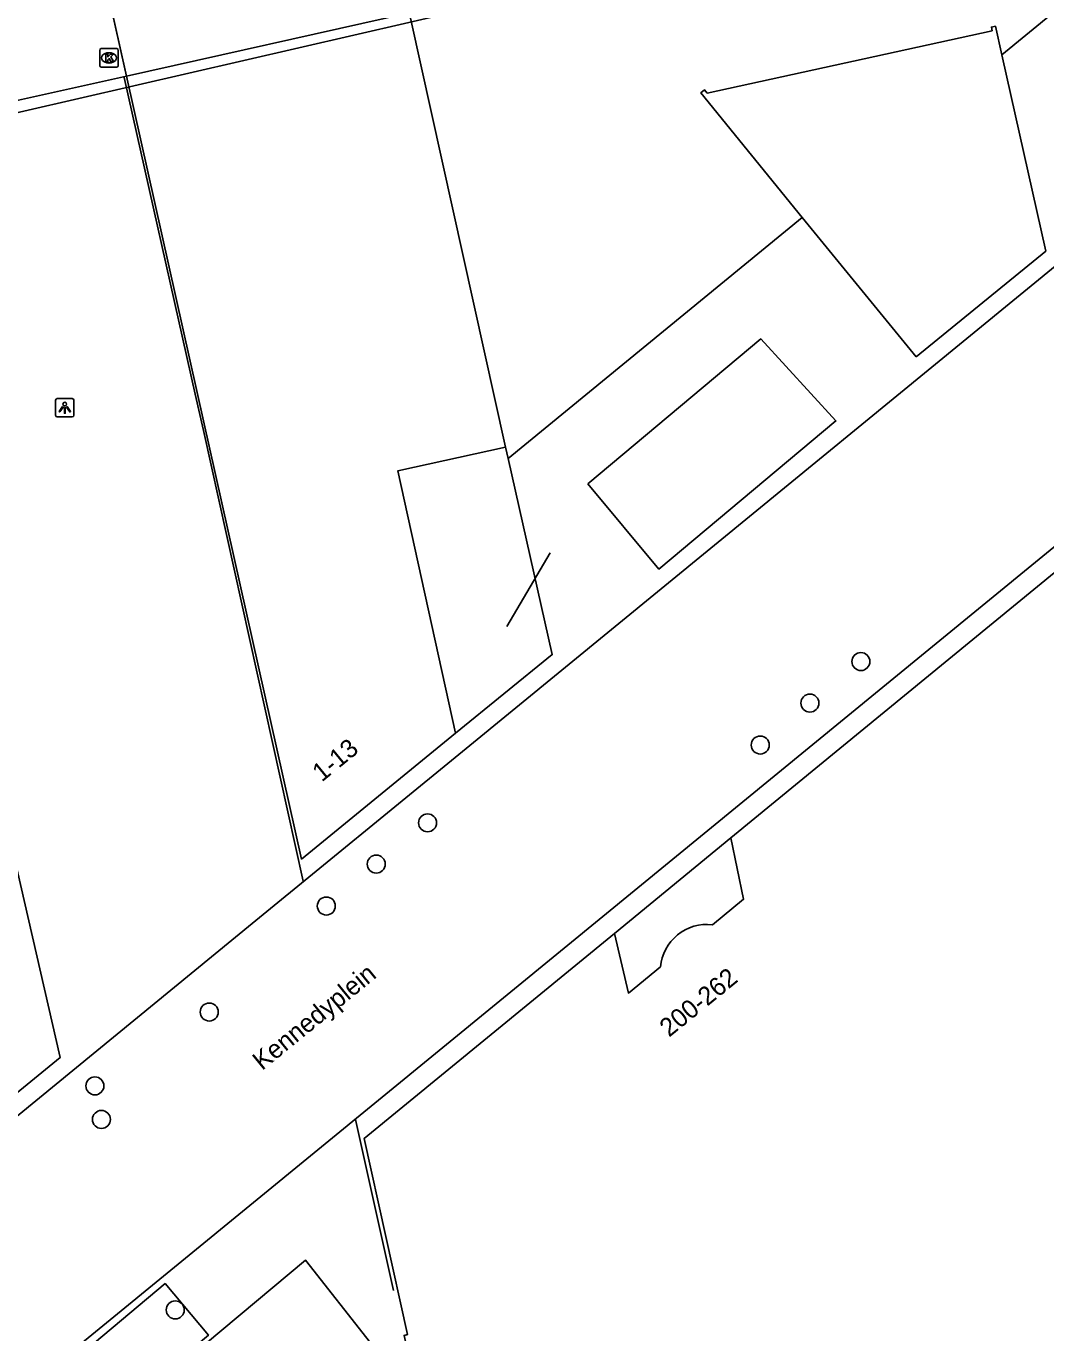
# Model space of a CAD drawing. Extents: x 160806 to 161707, y 383697 to 384148.
# Drawn here: x 161433.9 to 161489.3, y 383859.4 to 383930.4 of the extents above; entities that cross this region are included whole.
import ezdxf

# ---------------------------------------------------------------- set-up
doc = ezdxf.new("R2010")
doc.units = 0
for name, color, linetype in [('IMGEO_Boom', 7, 'Continuous'), ('IMGEO_Kolk', 7, 'Continuous'), ('IMGEO_Lage_trafo', 7, 'Continuous'), ('IMGEO_Lichtpunt', 7, 'Continuous'), ('IMGEO_Lijnafwatering', 7, 'Continuous'), ('IMGEO_Muur', 7, 'Continuous'), ('IMGEO_Openbare_ruimte_label', 7, 'Continuous'), ('IMGEO_Pand', 7, 'Continuous'), ('IMGEO_Pand_nummerreeks', 7, 'Continuous'), ('IMGEO_Pand_overbouw', 7, 'Continuous'), ('IMGEO_Pand_vergunning_verleend', 7, 'Continuous'), ('IMGEO_Rijbaan_lokaal_open', 7, 'Continuous'), ('IMGEO_Voetpad_open', 7, 'Continuous')]:
    doc.layers.add(name, color=color, linetype=linetype)

msp = doc.modelspace()

# ---------------------------------------------------------------- linework, layer by layer
at = {"layer": 'IMGEO_Boom'}
for centre in [(161479.28, 383895.862), (161476.511, 383893.603), (161473.815, 383891.327), (161455.746, 383887.101), (161452.959, 383884.86), (161450.245, 383882.583), (161443.887, 383876.827), (161437.673, 383872.817), (161438.028, 383870.992), (161442.039, 383860.652)]:
    msp.add_circle(centre, 0.489, dxfattribs=at)
at = {"layer": 'IMGEO_Kolk'}
for p, q in [((161437.942, 383928.219), (161437.942, 383929.071)), ((161438.017, 383929.145), (161438.869, 383929.145)), ((161438.43, 383928.925), (161438.455, 383928.925)), ((161438.943, 383929.071), (161438.943, 383928.219)), ((161438.869, 383928.145), (161438.017, 383928.145)), ((161438.453, 383928.365), (161438.428, 383928.365))]:
    msp.add_line(p, q, dxfattribs=at)
for points in [[(161437.942, 383928.219), (161437.942, 383929.071)], [(161438.017, 383929.145), (161438.869, 383929.145)], [(161438.263, 383928.845), (161438.386, 383928.845), (161438.386, 383928.694), (161438.516, 383928.845), (161438.68, 383928.845), (161438.534, 383928.694), (161438.687, 383928.445), (161438.535, 383928.445), (161438.45, 383928.609), (161438.386, 383928.542), (161438.386, 383928.445), (161438.263, 383928.445), (161438.263, 383928.845)], [(161438.943, 383929.071), (161438.943, 383928.219)], [(161438.869, 383928.145), (161438.017, 383928.145)]]:
    msp.add_lwpolyline(points, dxfattribs=at)
for centre, start, end in [((161438.019, 383929.069), 91.55205, 178.44795), ((161438.019, 383929.069), 91.55205, 178.44795), ((161438.867, 383929.069), 1.55205, 88.44795), ((161438.867, 383929.069), 1.55205, 88.44795), ((161438.019, 383928.221), 181.55205, 268.44795), ((161438.019, 383928.221), 181.55205, 268.44795), ((161438.867, 383928.221), 271.55205, 358.44795), ((161438.867, 383928.221), 271.55205, 358.44795)]:
    msp.add_arc(centre, 0.0765, start, end, dxfattribs=at)
for centre, major_axis, ratio, start_param, end_param in [((161438.429, 383928.645), (-0.387, 0.002), 0.722429, 4.712389, 7.853982), ((161438.454, 383928.645), (-0.39, 0.002), 0.717154, 1.570796, 4.712389)]:
    msp.add_ellipse(centre, major_axis=major_axis, ratio=ratio, start_param=start_param, end_param=end_param, dxfattribs=at)
at = {"layer": 'IMGEO_Lage_trafo'}
msp.add_lwpolyline([(161482.285, 383912.417), (161476.093, 383919.982), (161470.586, 383926.74), (161470.783, 383926.909), (161470.932, 383926.734), (161486.412, 383930.118), (161486.368, 383930.313), (161486.593, 383930.363), (161486.939, 383928.817), (161489.323, 383918.15), (161482.285, 383912.417)], dxfattribs=at)
at = {"layer": 'IMGEO_Lichtpunt'}
for p, q in [((161436.441, 383910.141), (161435.633, 383910.141)), ((161436.441, 383910.141), (161435.633, 383910.141)), ((161435.539, 383910.046), (161435.539, 383909.239)), ((161435.539, 383910.046), (161435.539, 383909.239)), ((161436.535, 383909.239), (161436.535, 383910.046)), ((161436.535, 383909.239), (161436.535, 383910.046)), ((161435.633, 383909.145), (161436.441, 383909.145)), ((161435.633, 383909.145), (161436.441, 383909.145))]:
    msp.add_line(p, q, dxfattribs=at)
for points in [[(161435.913, 383909.71), (161435.952, 383909.682), (161435.764, 383909.42), (161435.726, 383909.447), (161435.913, 383909.71)], [(161436.015, 383909.662), (161436.062, 383909.662), (161436.062, 383909.34), (161436.015, 383909.34), (161436.015, 383909.662)], [(161436.125, 383909.682), (161436.163, 383909.709), (161436.35, 383909.447), (161436.311, 383909.419), (161436.125, 383909.682)]]:
    msp.add_lwpolyline(points, dxfattribs=at)
msp.add_circle((161436.038, 383909.844), 0.0994, dxfattribs=at)
for centre, start, end in [((161435.633, 383910.046), 90, 180), ((161435.633, 383910.046), 90, 180), ((161436.441, 383910.046), 0, 90), ((161436.441, 383910.046), 0, 90), ((161435.633, 383909.239), 180, 270), ((161435.633, 383909.239), 180, 270), ((161436.441, 383909.239), 270, 0), ((161436.441, 383909.239), 270, 360)]:
    msp.add_arc(centre, 0.0946, start, end, dxfattribs=at)
at = {"layer": 'IMGEO_Lijnafwatering'}
for points in [[(161502.28, 383941.387), (161486.939, 383928.817)], [(161443.569, 383908.415), (161443.126, 383910.384), (161439.258, 383927.569)], [(161498.731, 383924.609), (161485.032, 383913.398)], [(161476.093, 383919.982), (161460.12, 383906.88)], [(161485.032, 383913.398), (161471.334, 383902.187)], [(161448.986, 383883.942), (161443.569, 383908.415)], [(161497.266, 383908.212), (161480.466, 383894.464)], [(161471.334, 383902.187), (161457.635, 383890.976)], [(161460.045, 383897.758), (161462.396, 383901.756)], [(161480.466, 383894.464), (161463.161, 383880.303)], [(161457.635, 383890.976), (161446.22, 383881.633)], [(161446.22, 383881.633), (161430.238, 383868.553)], [(161463.161, 383880.303), (161446.281, 383866.489)], [(161451.826, 383870.993), (161453.9, 383861.703)], [(161446.281, 383866.489), (161429.508, 383852.763)]]:
    msp.add_lwpolyline(points, dxfattribs=at)
at = {"layer": 'IMGEO_Muur'}
msp.add_lwpolyline([(161433.038, 383926.234), (161439.383, 383927.651)], dxfattribs=at)
at = {"layer": 'IMGEO_Pand'}
for points in [[(161439.383, 383927.651), (161454.756, 383931.084)], [(161454.819, 383930.799), (161459.978, 383907.51)], [(161457.261, 383891.97), (161448.9, 383885.137), (161443.236, 383910.469), (161439.383, 383927.651)], [(161457.261, 383891.97), (161454.121, 383906.21), (161459.978, 383907.51)], [(161472.218, 383886.284), (161492.387, 383902.807)], [(161472.218, 383886.284), (161472.911, 383882.95), (161471.213, 383881.568)], [(161459.23, 383837.816), (161454.467, 383859.266), (161454.649, 383859.314), (161452.306, 383869.965), (161465.897, 383881.096)], [(161468.392, 383879.273), (161466.655, 383877.86), (161465.897, 383881.096)], [(161445.17, 383845.408), (161444.948, 383845.529), (161445.128, 383845.88), (161435.296, 383851.477), (161434.859, 383851.112), (161434.699, 383851.304), (161449.115, 383863.351), (161452.644, 383858.861), (161445.17, 383845.408)]]:
    msp.add_lwpolyline(points, dxfattribs=at)
msp.add_arc((161470.927, 383879.039), 2.546, 83.54263, 174.71692, dxfattribs=at)
at = {"layer": 'IMGEO_Pand_overbouw'}
for points in [[(161576.544, 383863.524), (161556.299, 383953.974), (161403.923, 383918.874), (161417.58, 383859.039), (161456.542, 383836.683)], [(161439.383, 383927.651), (161454.756, 383931.084), (161454.475, 383932.341), (161452.563, 383940.896), (161451.9, 383943.862), (161451.327, 383946.429), (161435.971, 383942.989), (161436.543, 383940.418), (161437.201, 383937.461), (161439.099, 383928.931)], [(161459.978, 383907.51), (161454.121, 383906.21), (161457.261, 383891.97), (161462.516, 383896.238), (161460.12, 383906.88)]]:
    msp.add_lwpolyline(points, close=True, dxfattribs=at)
for points in [[(161471.213, 383881.568), (161472.911, 383882.95), (161472.218, 383886.284), (161465.897, 383881.096)], [(161465.897, 383881.096), (161466.655, 383877.86), (161468.392, 383879.273)]]:
    msp.add_lwpolyline(points, dxfattribs=at)
msp.add_arc((161470.927, 383879.039), 2.546, 83.54263, 174.71692, dxfattribs=at)
at = {"layer": 'IMGEO_Pand_vergunning_verleend'}
for points in [[(161464.441, 383905.505), (161473.848, 383913.38), (161477.926, 383908.926), (161468.313, 383900.88), (161464.441, 383905.505)], [(161431.877, 383854.037), (161441.49, 383862.083), (161443.842, 383859.273), (161434.229, 383851.226), (161431.877, 383854.037)]]:
    msp.add_lwpolyline(points, dxfattribs=at)
at = {"layer": 'IMGEO_Rijbaan_lokaal_open'}
for points in [[(161439.383, 383927.651), (161437.201, 383937.461), (161436.914, 383938.751)], [(161433.038, 383926.234), (161439.383, 383927.651)]]:
    msp.add_lwpolyline(points, dxfattribs=at)
at = {"layer": 'IMGEO_Voetpad_open'}
for points in [[(161459.978, 383907.51), (161460.12, 383906.88), (161462.516, 383896.238), (161457.261, 383891.97)], [(161465.897, 383881.096), (161472.218, 383886.284)], [(161429.23, 383880.342), (161429.044, 383881.036), (161433.434, 383884.613), (161435.782, 383874.353), (161429.991, 383869.63)]]:
    msp.add_lwpolyline(points, dxfattribs=at)

# ---------------------------------------------------------------- texts
at = {"layer": 'IMGEO_Openbare_ruimte_label'}
msp.add_text('Kennedyplein', height=1, rotation=39.19669, dxfattribs=at).set_placement((161446.756, 383873.621))
at = {"layer": 'IMGEO_Pand_nummerreeks'}
for s, rotation, p in [('1-13', 39.25778, (161449.999, 383889.289)), ('200-262', 39.13253, (161468.862, 383875.427))]:
    msp.add_text(s, height=1, rotation=rotation, dxfattribs=at).set_placement(p)

doc.saveas('drawing.dxf')
